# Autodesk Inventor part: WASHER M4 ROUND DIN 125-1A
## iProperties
Created: 2006-02
Part Number: WASHER M4 ROUND DIN 125-1A
Material: Steel, Mild
Description: Washer
Document SubType Name: Modeling
Standard: DIN 125
Designer: Andy Moles
Standards Organization: DIN
Language: en-US
Size Designation: A 4.3
Categories: <MemberInstance><Categories><Category DisplayName="Fasteners" InternalName="e4da775c-781d-43d5-af7c-5136215cf5a6" Mnemonic="FSTN"><Category DisplayName="Washers
Density: 7.86 g/cm^3
Mass: 0.308711 g
Surface Area: 1.31617 cm^2
Volume: 0.0392762 cm^3
IsCustomPart: 1
Author: Andy Moles
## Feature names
1. Body [Extrusion]
